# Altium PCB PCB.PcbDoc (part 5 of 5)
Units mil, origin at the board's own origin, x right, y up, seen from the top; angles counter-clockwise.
Board outline 8070.87 x 4448.94 mil, 4 copper layers (Top Layer, Layer 1, Layer 2, Bottom Layer), stack 23.756 mil thick; 263 components, 330 nets, 1677 pads, 1186 vias.
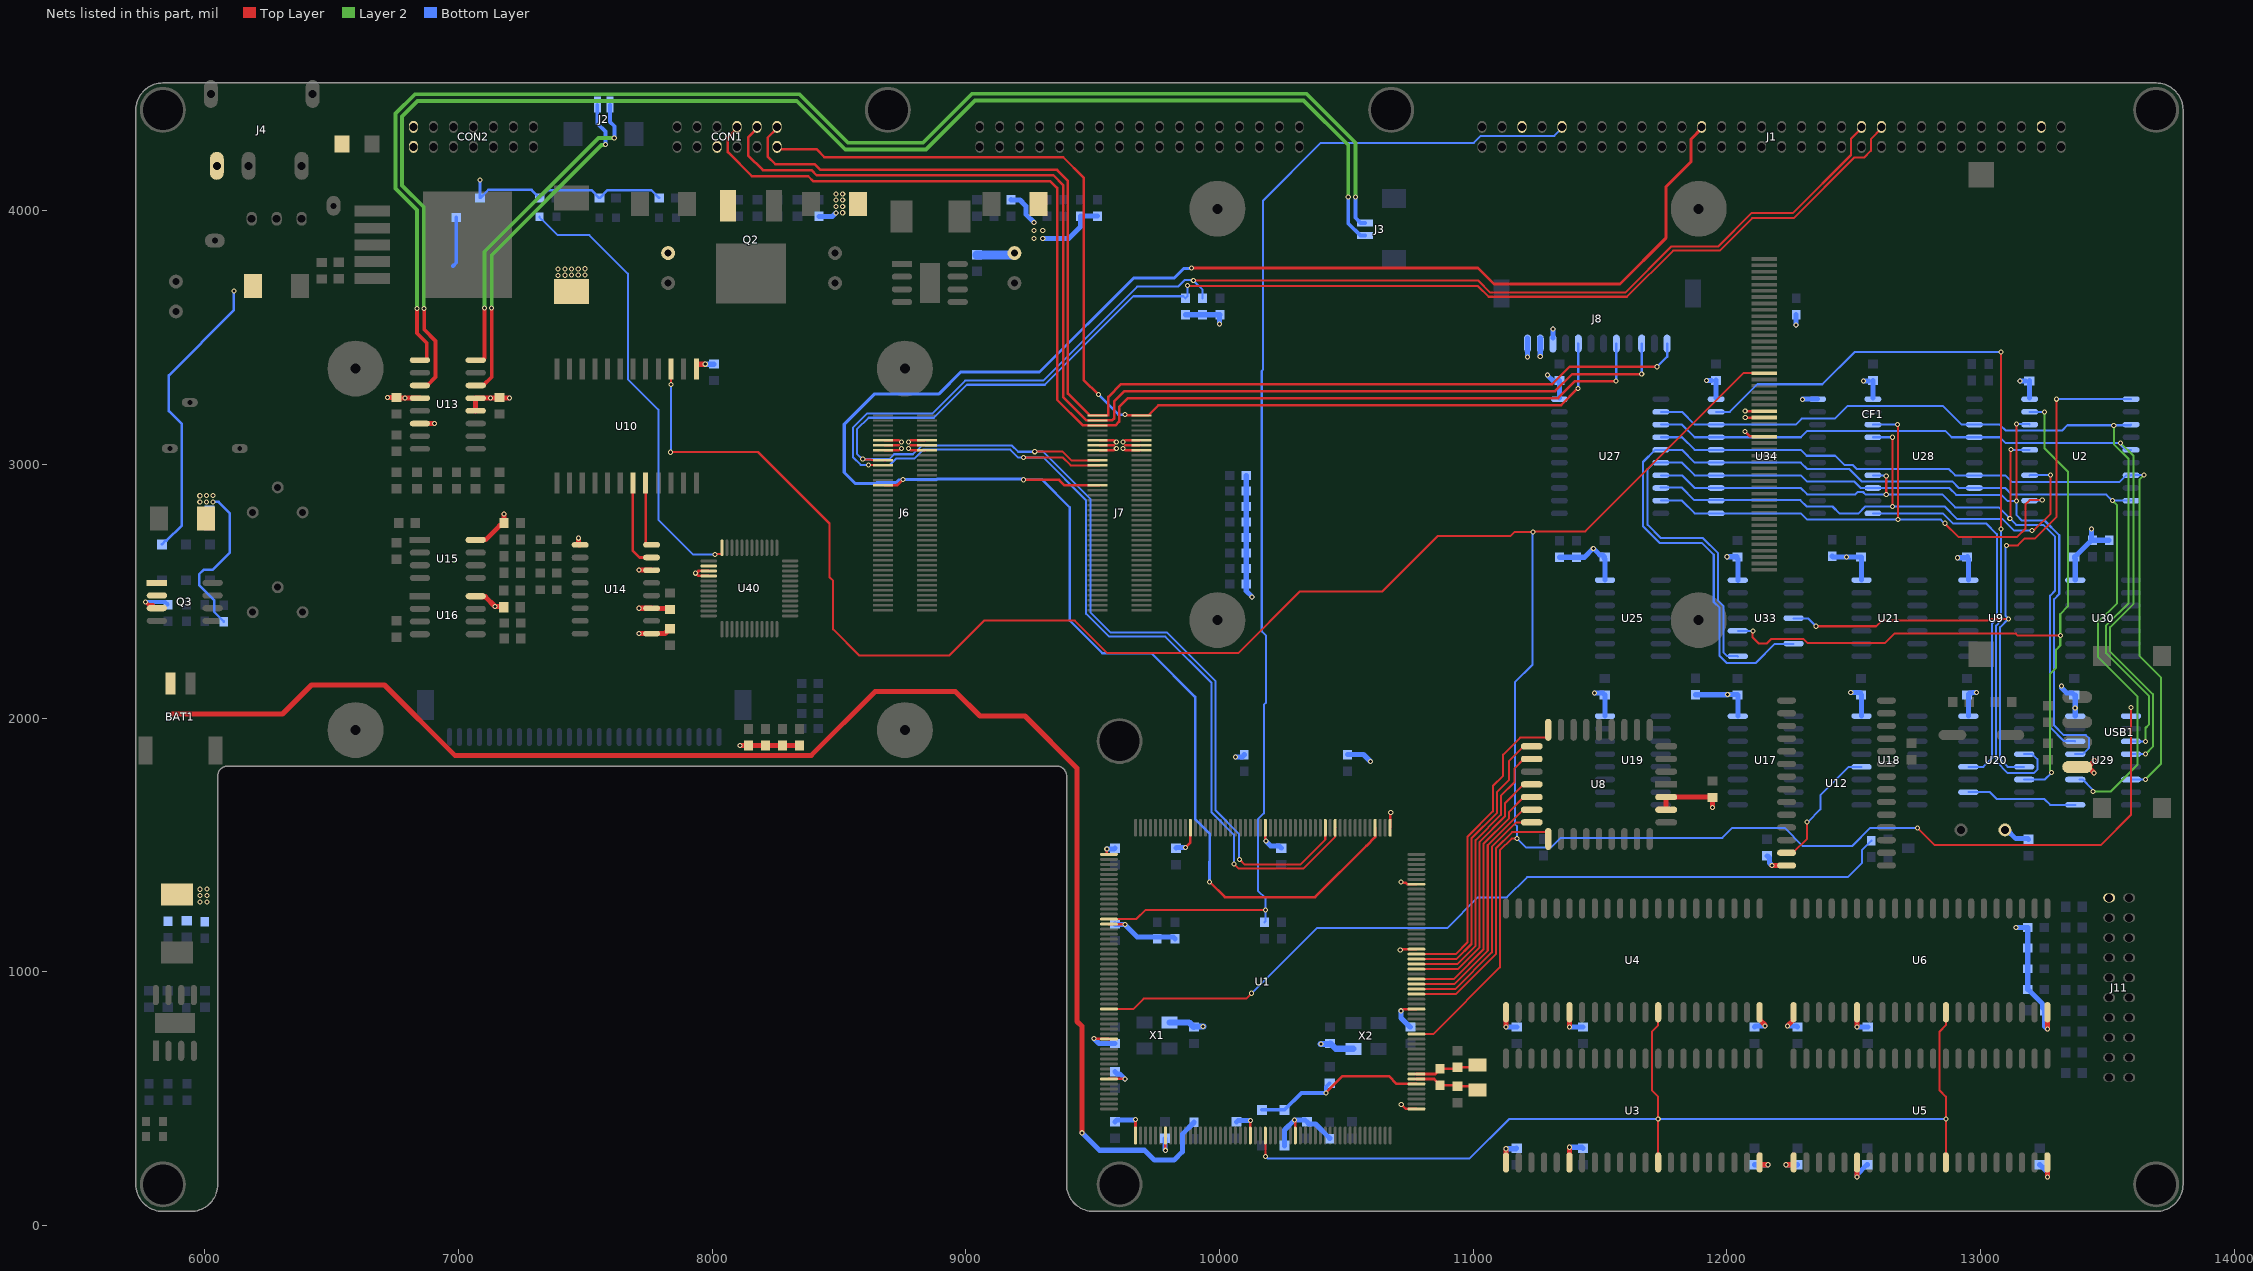
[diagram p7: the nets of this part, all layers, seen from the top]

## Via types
v1: diameter 20, hole 12, Top Layer to Bottom Layer, tented both sides, 1165 vias
v2: diameter 19.68, hole 11.81, Top Layer to Bottom Layer, tented both sides, 10 vias
v3: diameter 27.56, hole 27.56, Top Layer to Bottom Layer, 4 vias
v4: diameter 35.43, hole 35.43, Top Layer to Bottom Layer, 2 vias
v5: diameter 55.12, hole 55.12, Top Layer to Bottom Layer, 2 vias
v6: diameter 66.93, hole 66.93, Top Layer to Bottom Layer, 2 vias
v7: diameter 78.74, hole 78.74, Top Layer to Bottom Layer, 1 vias

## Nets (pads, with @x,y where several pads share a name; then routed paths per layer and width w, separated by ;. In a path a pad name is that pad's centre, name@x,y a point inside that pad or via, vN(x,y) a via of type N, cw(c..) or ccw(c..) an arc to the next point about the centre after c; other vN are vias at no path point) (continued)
RESET#: CF1.41 U1.120 U10.3 U29.1 | length 11067.3
  Top Layer w8: v1(7836,3048) 7837,3049 8181,3049 8463,2767 8463,2555 8477,2541 8477,2350 8581,2246 8934,2246 9072,2384 9430,2384 9558,2256 10073.52,2256 10316.52,2499 10642,2499 10860,2717 11147,2717 11164,2734 v1(11236,2734) 11238.3,2736.3 11442.41,2736.3 12065.76,3359.65 CF1.41@12147.64,3359.65 ; v1(7838,3315) U10.3@7838,3375.82 ; U1.120@10776.77,754.25 10842.62,754.25 11106,1017.63 11106,1478.98 11152,1524.98 v1(11174,1525) ; v1(12753,1566) 12819,1500 13476,1500 13594,1618 v1(13594,2042)
  Bottom Layer w8: v1(7836,3048) 7838,3050 v1(7838,3315) ; v1(11236,2734) 11234.42,2732.43 11234.42,2210.43 11165,2141 11165,1582 11174,1573 v1(11174,1525) 11210,1489 11306,1489 11345,1528 11982.63,1528 12021.63,1567 12228.37,1567 12300.37,1495 12494,1495 12566,1567 12752,1567 v1(12753,1566) ; U29.1@13594.02,2007.8 v1(13594,2042)
RPA: U20.4 U34.19 | length 3133
  Top Layer w8: v1(13081,2746) v1(13081,3444)
  Bottom Layer w8: U34.19@11958.27,3207.09 12012.09,3207.09 12121,3316 12377,3316 12504,3443 13080,3443 v1(13081,3444) ; v1(13081,2746) 13081,2383.63 13062,2364.63 13062,1829 13108,1783 13211,1783 13225,1797 13225,1838 13205.2,1857.8 U20.4@13172.76,1857.8
RPB: U2.1 U20.5 U33.4 | length 2844.4
  Top Layer w8: v1(12352,2362) 12589,2362 12611,2384 13028.74,2384 13035.74,2391 v1(13111,2391) ; v1(13103,2681) 13147.89,2681 13173.89,2707 13214,2707 13301,2794 v1(13301,3257)
  Bottom Layer w8: U33.4@12263.78,2392.52 12321.48,2392.52 v1(12352,2362) ; v1(13103,2681) 13100.7,2678.7 13100.7,2672.02 13099,2670.31 13099,2403 v1(13111,2391) 13078,2358 13078,1837 13107.2,1807.8 U20.5@13172.76,1807.8 ; v1(13301,3257) v1(13301,3257) 13594.44,3257.05 U2.1@13594.49,3257.09
RPC: U2.19 U20.6 U33.10 | length 3014.2
  Top Layer w8: v1(12104,2343) 12101.7,2340.7 12101.7,2317.92 12125.63,2294 12158.49,2294 12176.49,2312 12302.26,2312 12319.26,2295 12623,2295 12661,2333 13139.63,2333 13147.63,2325 13315,2325 v1(13316,2326)
  Layer 2 w8: v1(13252.85,3206.96) 13253,3206.8 13253,3064 13345,2972 13345,2440 13315,2410 13315,2326 13315,2286 13299,2270 13299,2198.37 13275,2174.37 13275,1794.25 13281,1788.25 v1(13281,1785)
  Bottom Layer w8: U33.10@12043.78,2342.52 12044.02,2342.76 12103.76,2342.76 v1(12104,2343) ; U20.6@13172.76,1757.8 13253.8,1757.8 v1(13281,1785) ; U2.19@13194.49,3207.09 13194.56,3207.03 v1(13252.85,3206.96) v1(13252.85,3206.96)
SMEMR#: J1.40 J6.60 J7.60 R59.1 U1.168 | length 8467.4
  Top Layer w8: v1(8616.94,2998) 8617.96,2996.98 J6.60@8680.18,2996.98 ; v1(9228,3027.86) 9381.51,3027.86 9413.31,2996.06 J7.60@9527.56,2996.06 ; v1(9897,3725) 11020.25,3725 11068.25,3677 11600,3677 11782,3859 11966,3859 12099,3992 12262.26,3992 12490,4219.74 12490,4283.31 12531.5,4324.8 J1.40@12531.5,4330.71 ; v1(10058,1424) 10076,1406 10330.3,1406 10455.96,1531.67 10455.96,1566.83 U1.168@10456.69,1567.56
  Bottom Layer w8: v1@8616,2998.38 8701.38,2998.38 8727,3024 8798.37,3024 8832.37,3058 9175.63,3058 9205.76,3027.86 v1(9228,3027.86) 9304.88,3027.86 9475,2857.75 9475,2411.05 9565.4,2320.65 9787.35,2320.65 9969,2139 9969,1628.92 10057.28,1540.64 10057.28,1424.72 v1(10058,1424) ; v1(8616.94,2998) 8616.57,2998.38 8585.89,2998.38 8555,3029.27 8555,3144.63 8610.37,3200 8868,3200 8998,3330 9305.08,3330 9676.08,3701 9836.63,3701 9862.63,3727 9895,3727 v1(9897,3725) 9934,3688 R59.1@9934,3655
SMEMW#: J1.42 J6.62 J7.62 R58.1 U1.170 | length 8354.5
  Top Layer w8: v1(8594,3021.38) 8595.38,3020 8626.06,3020 8629.58,3016.47 8680.38,3016.47 J6.62@8681.09,3015.76 ; v1(9272,3050) 9382,3050 9416.25,3015.75 J7.62@9527.56,3015.75 ; v1(9874,3705) 9876,3703 11019.63,3703 11061.63,3661 11606.63,3661 11788.63,3843 11972.63,3843 12100.63,3971 12263.89,3971 12502.89,4210 12542,4210 12568,4236 12568,4282.57 12610.24,4324.8 J1.42@12610.24,4330.71 ; v1(10079.28,1442.85) 10100.13,1422 10318.51,1422 10417.32,1520.81 U1.170@10417.32,1567.56
  Bottom Layer w8: v1@8593.5,3020.38 8698.38,3020.38 8718,3040 8791.75,3040 8825.75,3074 9182.25,3074 9206.32,3049.93 9271.93,3049.93 v1(9272,3050) ; v1(8594,3021.38) 8591.62,3021.38 8571,3042 8571,3138 8617,3184 8874.63,3184 9004.63,3314 9311.71,3314 9660.71,3663 9858,3663 R58.1@9866,3655 9874,3663 v1(9874,3705) ; v1@9272.07,3050 9305.37,3050 9491,2864.37 9491,2417.68 9571.68,2337 9793.63,2337 9985,2145.63 9985,1635.55 10078,1542.55 10078,1444.13 v1(10079.28,1442.85)
SMP1: U10.20 U14.8 | length 264.1
  Top Layer w10: U10.20@7738,2927 7738,2688.54 7743.54,2683 U14.8@7761.34,2683
SMP2: U10.19 U14.7 | length 352.1
  Top Layer w10: U10.19@7688,2927 7688,2659 7714,2633 U14.7@7761.34,2633
SPKL+: J3.1 U13.1 | length 5444.9
  Top Layer w15: v1(6836,3614) 6836.96,3613.04 6836.96,3517.04 6875.11,3478.89 6875.11,3414.43 6871.87,3411.2 U13.1@6848,3411.2
  Layer 2 w15: v1(6836,3614) 6836,4003 6751.84,4087.16 6751.84,4382.84 6828.16,4459.16 8344.84,4459.16 8536,4268 8832,4268 9025.16,4461.16 10342.84,4461.16 10536,4268 v1(10536,4055)
  Bottom Layer w15: v1(10536,4055) 10536,3972.35 10556.26,3952.09 J3.1@10573.98,3952.09
SPKL-: J3.2 U13.3 | length 5540.1
  Top Layer w15: U13.3@6848,3311.2 6877,3311.2 6910,3344.2 6910,3487 6864.96,3532.04 6864.96,3613.04 v1(6864,3614)
  Layer 2 w15: v1(6864,3614) 6863.16,3614.84 6863.16,4014.84 6778,4100 6778,4372 6839,4433 8334,4433 8525.16,4241.84 8842.84,4241.84 9036,4435 10332,4435 10508,4259 v1(10508,4054)
  Bottom Layer w15: v1(10508,4054) 10508,3950.35 10556.26,3902.09 J3.2@10573.98,3902.09
SPKR: R3.1 U1.32 | length 3311
  Top Layer w8: U1.32@9564.65,852.68 9659.68,852.68 9701,894 10106,894 v1(10127,915)
  Bottom Layer w8: v1(10127,915) 10384,1172 10898,1172 11019,1293 11133,1293 11213,1373 12478,1373 12533,1428 12533,1478.5 12570,1515.5 R3.1@12570,1517
SPKR+: J2.1 U13.16 | length 1291.7
  Top Layer w15: U13.16@7068,3411.2 7095.11,3411.2 7103.08,3419.17 v1@7103.08,3615.72
  Layer 2 w15: v1(7103.08,3617.07) 7103.08,3838.08 7552.4,4287.4 v1(7614.17,4287.4)
  Bottom Layer w15: J2.1@7597.44,4418.31 7597.44,4350.56 7615,4333 7615,4288.23 v1(7614.17,4287.4)
SPKR-: J2.2 U13.14 | length 1357.7
  Top Layer w15: U13.14@7068,3311.2 7070.29,3313.48 7099.29,3313.48 7131,3345.2 7131,3616.92 v1(7131.08,3617)
  Layer 2 w15: v1@7131,3617.07 7131,3826 7564.44,4259.44 7578.22,4259.44 v1(7579.17,4260.4)
  Bottom Layer w15: J2.2@7547.44,4418.31 7547.44,4344.56 7580,4312 7580,4261.23 v1(7579.17,4260.4)
SYSCLK: J1.24 J6.52 J7.52 U1.160 | length 8263.9
  Top Layer w10: J6.52@8681.1,2917.32 8729.66,2917.32 v1(8752,2939.66) ; v1(9228,2939.6) 9261.67,2939.6 9262.47,2938.8 9368.2,2938.8 9389.68,2917.32 J7.52@9527.56,2917.32 ; v1(9961,1354) 9962,1354 10022,1294 10377,1294 10579,1496 10579.19,1496 10613.83,1530.63 10613.83,1567.21 U1.160@10614.17,1567.56
  Top Layer w12: v1(9890,3774) 11019.34,3774 11082.34,3711 11579,3711 11760,3892 11760,4094 11860,4194 11860,4283.23 11901.57,4324.8 J1.24@11901.57,4330.71
  Bottom Layer w10: v1(9228,2939.6) 9228.93,2938.66 9302.16,2938.66 9410,2830.82 9410,2384.12 9538.62,2255.51 9731.92,2255.51 9904,2083.43 9904,1602 9961.5,1544.5 9961.5,1434.82 9961,1434.32 v1(9961,1354)
  Bottom Layer w12: v1(8752,2939.66) 8750.47,2938.13 8735.68,2938.13 8725.77,2928.23 8647.97,2928.23 8644.75,2925 8564.29,2925 8521,2968.29 8521,3158.71 8639.29,3277 8893.37,3277 8980.37,3364 9290.99,3364 9661.99,3735 9743.62,3735 9822.54,3735 9860.54,3773 9889,3773 v1(9890,3774) ; v1@8752.07,2939.66 8884.7,2939.66 8888.03,2943 9222.43,2943 9225.84,2939.6 v1(9228,2939.6)
TC: J1.10 R10.2 U1.14 | length 4815.6
  Top Layer w8: U1.14@9564.65,1207.01 9565.37,1207.74 9672.85,1207.74 9709.11,1244 v1(10182,1244)
  Bottom Layer w8: R10.2@10178,1195 10182,1199 v1(10182,1244) 10182,1290 10152,1320 10152,1601 10175,1624 10175,2052.33 10183,2060.33 10183,2326 10167,2342 10167,3368.94 10172,3373.94 10172,4040 10399.97,4267.97 11003.5,4267.97 11030.62,4295.09 11320.68,4295.09 11350.39,4324.8 J1.10@11350.39,4330.71
TD0: U2.3 U27.2 U28.3 U29.3 U34.18 | length 3393.6
  Layer 2 w8: v1(13526,3153) 13526,3079.89 13584,3021.89 13584,2453.12 13496,2365.12 13496,2255.37 13664,2087.37 13664,1973.89 13651,1960.89 v1(13651,1908)
  Bottom Layer w8: U27.2@11740.16,3207.09 11823.91,3207.09 11873.91,3157.09 U34.18@11958.27,3157.09 12272.09,3157.09 12295.09,3180.09 12426.09,3180.09 12477,3231 12852,3231 12925.91,3157.09 U28.3@12976.38,3157.09 13076.91,3157.09 13101,3133 13322,3133 13343.42,3154.42 13591.81,3154.42 U2.3@13594.49,3157.09 ; U29.3@13594.11,1907.9 13650.9,1907.9 v1(13651,1908)
TD1: U2.5 U27.3 U28.4 U29.4 U34.17 | length 3345.2
  Layer 2 w8: v1(13553,3084) 13604,3033 13604,2450.49 13512,2358.49 13512,2262 13680,2094 13680,1887 v1(13651,1858)
  Bottom Layer w8: U27.3@11740.16,3157.09 11823.91,3157.09 11873.91,3107.09 U34.17@11958.27,3107.09 12292.09,3107.09 12317,3132 12862,3132 12886.91,3107.09 U28.4@12976.38,3107.09 13076.91,3107.09 13100.5,3083.5 13552.5,3083.5 v1(13553,3084) 13555.3,3081.7 13555.3,3073.82 13572.02,3057.09 U2.5@13594.49,3057.09 ; U29.4@13594.11,1857.9 13650.9,1857.9 v1(13651,1858)
TD2: U2.7 U27.4 U28.7 U29.6 U34.16 | length 3313
  Layer 2 w8: v1(13645,2958) 13628,2941 13628,2244.37 13712,2160.37 13712,1819 v1(13651,1758)
  Bottom Layer w8: U27.4@11740.16,3107.09 11823.91,3107.09 11873.91,3057.09 U34.16@11958.27,3057.09 12291.91,3057.09 12314.91,3034.09 12427.79,3034.09 12463.89,2998 12496,2998 12512,2982 12876,2982 12900.91,2957.09 U28.7@12976.38,2957.09 13097.91,2957.09 13124,2931 13549.11,2931 13575.21,2957.09 U2.7@13594.49,2957.09 13594.94,2957.55 13644.55,2957.55 v1(13645,2958) ; U29.6@13594.11,1757.9 13650.9,1757.9 v1(13651,1758)
TD3: U2.9 U27.5 U28.8 U29.11 U33.6 U34.15 | length 4790.7
  Layer 2 w8: v1(13444,1710) 13513,1710 13620,1817 13620,2084.75 13463.03,2241.72 13463.03,2377.4 13539,2453.37 13539,2839 v1(13520.91,2857.09)
  Bottom Layer w8: U33.6@12263.78,2292.52 12189.52,2292.52 12114,2217 11999.63,2217 11972,2244.63 11972,2434.63 11949,2457.63 11949,2644.37 11902.37,2691 11735,2691 11670,2756 11670,3009.4 11717.69,3057.09 U27.5@11740.16,3057.09 11823.91,3057.09 11873.91,3007.09 U34.15@11958.27,3007.09 12291.91,3007.09 12317,2982 12482.37,2982 12531.37,2933 12889,2933 12914.91,2907.09 U28.8@12976.38,2907.09 13097.91,2907.09 13124,2881 13497,2881 v1(13520.91,2857.09) U2.9@13594.49,2857.09 ; U29.11@13391,1757.8 13403.02,1757.8 13441.7,1719.11 13441.7,1712.3 v1(13444,1710)
TD4: U2.18 U27.6 U28.13 U29.13 U33.8 U34.14 | length 4170
  Top Layer w8: v1(13142,3160) 13142.55,3159.45 13142.55,2855.49 v1(13143.1,2854.93)
  Bottom Layer w8: U33.8@12043.78,2242.52 12041.2,2245.1 12000.83,2245.1 11988,2257.92 11988,2441.25 11965,2464.25 11965,2651 11906,2710 11740,2710 11688.69,2761.31 11688.69,2981.69 11714.09,3007.09 U27.6@11740.16,3007.09 11823.91,3007.09 11873.91,2957.09 U34.14@11958.27,2957.09 12291.91,2957.09 12317,2932 12504,2932 12528.91,2907.09 U28.13@12576.38,2907.09 12877.91,2907.09 12904.91,2880.09 13082.91,2880.09 13108.07,2854.93 v1(13143.1,2854.93) 13143.1,2799.9 13164,2779 13253,2779 13311,2721 13311,2489 13291,2469 13291,1970.63 13328.63,1933 13416,1933 13429,1920 13429,1883 13403.8,1857.8 U29.13@13374.02,1857.8 ; v1(13142,3160) 13143.45,3158.55 13193.04,3158.55 U2.18@13194.49,3157.09
TD5: U2.16 U27.7 U28.14 U29.14 U34.13 | length 3019.7
  Top Layer w8: v1(12629,2881) v1(12629,2955) ; v1(13116,2787) 13118,2789 13118,3056 v1(13120,3058)
  Bottom Layer w8: U27.7@11740.16,2957.09 11823.91,2957.09 11873.91,2907.09 U34.13@11958.27,2907.09 12291.91,2907.09 12317,2882 12506.89,2882 12515.98,2891.09 12537.39,2891.09 12547.48,2881 12628,2881 12629,2882 12850,2882 12901,2831 13072,2831 v1(13116,2787) 13141,2762 13247.37,2762 13295,2714.37 13295,2502.89 13275,2482.89 13275,1964 13329.84,1909.16 13372.66,1909.16 U29.14@13374.02,1907.8 ; U28.14@12576.38,2957.09 12577.43,2956.05 12627.95,2956.05 v1(12629,2955) ; v1(13120,3058) 13120.45,3057.55 13194.04,3057.55 U2.16@13194.49,3057.09
TD6: U2.14 U27.8 U28.17 U34.12 | length 2245.8
  Top Layer w8: v1(12653,2834) 12653.5,2834.5 12653.5,3106.5 v1(12654,3107) ; v1(13204,2740) 13206.3,2742.3 13213.3,2742.3 13277,2806 v1(13277,2959)
  Bottom Layer w8: U27.8@11739,2909 11822.75,2909 11872.75,2859 11958.27,2859 12290.75,2859 12315.84,2833.91 12417.21,2833.91 12445.11,2806 12519,2806 12546.91,2833.91 12653,2833.91 12858.84,2833.91 12908.65,2784.09 13087.79,2784.09 13131.89,2740 v1(13204,2740) ; U28.17@12576.38,3107.09 12576.43,3107.05 v1(12654,3107) v1(12654,3107) ; U2.14@13194.49,2957.09 13195.44,2958.05 13276.05,2958.05 v1(13277,2959)
TD7: U2.12 U27.9 U28.18 U34.11 | length 2204.2
  Top Layer w8: v1(12674,3157) 12676,3155 12676,2783 v1(12675,2782) ; v1(12860,2768) 12860,2767 12913,2714 13145,2714 13178,2747 13178,2843 13194,2859 v1(13244,2859)
  Bottom Layer w8: U27.9@11740.16,2857.09 11823.91,2857.09 11873.91,2807.09 U34.11@11958.27,2807.09 12291.91,2807.09 12317,2782 v1(12675,2782) 12843.89,2782 12857.89,2768 v1(12860,2768) ; U28.18@12576.38,3157.09 12576.43,3157.05 v1(12674,3157) v1(12674,3157) ; U2.12@13194.49,2857.09 13195.44,2858.05 13243.05,2858.05 v1(13244,2859)
TURBO: U40.14
USBCS#: U12.27 U18.12 | length 506.7
  Top Layer w8: U12.27@12236.22,1468.9 12261.12,1468.9 12317,1524.78 v1(12317,1590)
  Bottom Layer w8: v1(12317,1590) 12319,1590 12369,1640 12369,1696 12480.8,1807.8 U18.12@12531.5,1807.8
V3.7V: BAT1.2 C29.1 L5.1 Q3.1 Q3.2 Q3.3 R2.1 R27.2 R133.1 R135.2 | length 6121.7
  Top Layer w15: v1(5766,2458) 5767.35,2458 5778.35,2447 5796,2447
  Top Layer w20: 5871.5,2015.75 6306.75,2015.75 6421,2130 6708.58,2130 6985.58,1853 8391,1853 8642,2104 8960,2104 9056,2008 9233.35,2008 9439,1802.35 9439,804 9458,785 v1(9458,365)
  Bottom Layer w15: v1(5766,2458) 5766.96,2457.04 5844.33,2457.04 5854.33,2447.04 R27.2@5854.33,2446.89
  Bottom Layer w20: v1(9458,365) 9527,296 9705,296 9744,257 9821,257 9854,290 9854,359.5 9900,405.5 R2.1@9900,407
  other v1: 5981.48,1275.33 6007.87,1275.59 5981.48,1300.22 6007.87,1300.48 5981.48,1325.11 6007.87,1325.37
VCC: C1.2 C2.2 C10.1 C11.1 C12.1 C13.1 C14.1 C15.1 C16.1 C17.1 C24.1 C25.1 C30.1 C31.1 C52.2 C54.2 C59.2 C60.2 C61.2 C68.1 C72.1 C73.1 C74.1 C75.1 C76.1 C77.1 C78.1 C80.1 C83.1 C84.1 C85.1 C86.1 C87.1 C88.1 C89.1 C90.1 C91.1 C92.1 C93.1 C94.1 C95.1 C96.1 C97.1 C98.1 C99.1 C100.1 C101.1 C102.1 C103.1 C104.2 C105.2 CF1.13 CF1.36 CF1.38 CON1.5 CON2.1 CON2.2 D4.K D5.K D12.A J1.6 J1.58 J6.65 J6.66 J6.67 J6.68 J6.69 J6.70 J7.65 J7.66 J7.67 J7.68 J7.69 J7.70 J8.1 J8.2 J8.3 J11.1 R1.1 R44.2 R45.2 R46.2 R47.2 R48.2 R49.2 R50.2 R51.2 R52.2 R53.2 R54.2 R55.2 R56.2 R57.2 R58.2 R59.2 R60.2 R61.2 R62.2 R63.2 R64.2 R65.2 R66.2 R67.2 R68.2 R69.2 R70.2 R100.1 R102.2 R103.2 R104.2 R105.2 R106.2 R107.2 R136.1 R137.1 R138.1 R139.1 SP1.1 U1.1 U1.15 U1.38 U1.46 U1.53 U1.59 U1.76 U1.85 U1.105 U1.125 U1.137 U1.150 U1.157 U1.182 U1.197 U2.20 U3.1 U3.6 U3.21 U4.1 U4.6 U4.21 U5.1 U5.6 U5.21 U6.1 U6.6 U6.21 U8.31 U8.32 U9.14 U10.1 U12.28 U13.4 U13.6 U13.12 U13.13 U14.1 U14.3 U14.6 U14.9 U15.8 U16.8 U17.16 U18.16 U19.16 U20.16 U21.14 U25.14 U27.20 U28.20 U29.16 U30.14 U33.14 U34.1 U34.20 U40.15 U40.16 USB1.VCC X1.4 X2.4 | length 11745.2
  Top Layer w10: v1(7934,2571) 7936.71,2571 7945.6,2579.9 7949.09,2579.9 ; U40.16@7986.57,2560.21 7986.22,2560.56 7947.15,2560.56 7938.45,2569.26 7949.09,2579.9 ; U40.15@7986.57,2579.9 7949.09,2579.9 ; J6.66@8681.1,3055.12 8736.49,3055.12 ; J6.68@8681.1,3074.8 8736.49,3074.8 ; J6.70@8681.1,3094.49 8736.49,3094.49 ; 8783.2,3055.12 J6.65@8838.58,3055.12 ; 8783.2,3074.8 J6.67@8838.58,3074.8 ; 8783.2,3094.49 J6.69@8838.58,3094.49 ; v1(9506,736) 9507.09,734.91 9564.47,734.91 U1.38@9564.73,734.65 ; J7.66@9527.56,3055.12 9582.94,3055.12 ; J7.68@9527.56,3074.8 9582.94,3074.8 ; J7.70@9527.56,3094.49 9582.94,3094.49 ; v1(9556,1484) 9556,1463.75 9556.75,1463 U1.1@9564.73,1463 ; U1.46@9564.73,577.17 v1@9627.12,577.17 ; U1.15@9564.82,1187.32 9565.17,1186.98 9625.76,1186.98 v1(9627,1185.74) ; 9629.65,3055.12 J7.65@9685.04,3055.12 ; 9629.65,3074.8 J7.67@9685.04,3074.8 ; 9629.65,3094.49 J7.69@9685.04,3094.49 ; U1.53@9669.2,354.42 v1@9669.2,416.8 ; v1(9787,296) 9787.2,296.2 9787.2,354.3 U1.59@9787.4,354.5 ; v1(9866,1490) 9885.48,1509.48 9885.48,1567.21 U1.197@9885.83,1567.56 ; U1.76@10122.02,354.35 v1(10122,414) ; U1.182@10181.19,1567.47 10181.45,1567.21 10181.45,1516.55 v1(10183,1515) ; v1(10296.9,416) 10296.9,413.29 10299.21,410.98 U1.85@10299.21,354.5 ; U1.157@10673.31,1567.47 U1.157@10673.23,1567.56 10673.23,1622.98 10675.54,1625.29 v1(10675.54,1628) ; v1(10713,1086) 10715.71,1086 10718.6,1088.9 U1.137@10776.5,1088.9 ; v1(10716,846) 10718.71,846 10725.38,852.68 10776.6,852.68 U1.125@10776.68,852.59 ; v1(10716,1353) 10717.91,1351.09 10733.91,1351.09 10739.85,1345.15 10776.25,1345.15 U1.150@10776.68,1344.72 ; v1(10717,477) 10734.68,459.32 10776.25,459.32 U1.105@10776.68,458.89 ; v1(12072,3130) 12090.1,3111.9 12145.39,3111.9 CF1.36@12147.55,3109.73 ; v1(12073,3210) 12073.18,3209.82 12147.46,3209.82 CF1.38@12147.64,3209.65 ; v1@12073.27,3184.73 CF1.13@12147.55,3184.73
  Top Layer w20: v1(6721,3263) 6755.13,3263 C54.2@6755.91,3263.78 6758.68,3261 v1(6790,3261) ; v1@6787.22,3261.58 6847.62,3261.58 U13.4@6848,3261.2 ; U13.6@6848,3161.2 6848.2,3161 v1(6905,3161) ; U16.8@7068,2480.38 7097.08,2480.38 7099.08,2478.38 7105.62,2478.38 v1(7144,2440) 7176.02,2440 C68.1@7179.02,2437 ; U15.8@7068,2702.38 7068.77,2703.14 7107.14,2703.14 7162.38,2758.38 7170.99,2758.38 7179.49,2766.88 C61.2@7179.49,2768.38 7179,2768.87 v1(7179,2805) ; U13.12@7068,3211.2 U13.13@7068,3261.2 v1@7129.78,3261.2 ; v1(7127,3261) 7158.64,3261 C52.2@7161.42,3263.78 ; C52.2@7161,3261.2 7200.8,3261.2 v1(7201,3261) ; v1(7474,2709) 7474,2683.92 7474.92,2683 U14.9@7480,2683 ; v1(7711,2333) U14.1@7761.34,2333 7761.72,2333.38 7813.88,2333.38 7832.5,2352 C60.2@7834,2352 ; v1(7711,2433) U14.3@7761.34,2433 7761.72,2432.62 7829.63,2432.62 C59.2@7834.25,2428 ; v1(7711,2583) U14.6@7761.34,2583 ; U10.1@7938,3375.82 7938,3395 v1(7973,3395) ; v1(8110,1892) R48.2@8210.67,1892 R47.2@8277.33,1892 R46.2@8344,1892 ; U3.1@11130,248 v1(11130,302) ; v1(11130,782) U4.1@11130,840 ; U3.6@11380,248 11380,307 v1(11381,308) ; v1(11380,782) U4.6@11380,840 ; U8.31@11762.41,1639.58 U8.31@11761.46,1638.62 U8.32@11761.46,1688.62 11942.38,1688.62 C31.1@11944,1687 v1(11944,1647) ; U3.21@12130,248 12130,240.85 12131.85,239 v1(12163,239) ; U4.21@12130,840 12130,810.92 12151,789.92 v1(12151,786) ; v1(12179,1419) 12179.1,1418.9 U12.28@12236.22,1418.9 ; v1(12234,239) 12262.15,239 12264,240.85 U5.1@12264,248 ; v1(12239,786) 12264,811 U6.1@12264,840 ; v1(12514,190) U5.6@12514,248 ; v1(12514,782) U6.6@12514,840 ; v1(13264,190) U5.21@13264,248 ; v1(13264,774) U6.21@13264,840 ; USB1.VCC@13421,1809 13426,1809 v1(13449,1832) ; USB1.VCC@13422.78,1809 13447.78,1784 v1(13448,1784)
  Bottom Layer w8: C73.1@12528.94,2634.94 C73.1@12529,2635 C73.1@12531.5,2632.5
  Bottom Layer w10: v1(7085,4122) R139.1@7085,4051 7086.5,4051 7117.5,4082 7288.17,4082 7319.17,4051 R138.1@7320.67,4051 7322.17,4051 7352.67,4081.5 7524.33,4081.5 7554.83,4051 R137.1@7556.33,4051 7557.83,4051 7588.33,4081.5 7760,4081.5 7790.5,4051 R136.1@7792,4051
  Bottom Layer w20: v1(7973,3395) 8007,3395 C105.2@8008,3396 ; R57.2@8422,3978 8474.64,3978 v1(8488.61,3991.97) ; R100.1@9177.86,4044 9179.5,4042.36 9213.64,4042.36 9237,4019 9237,3986.35 v1(9269.61,3953.74) ; v1(9303.61,3890.24) 9406.24,3890.24 9452.67,3936.67 R62.2@9452.67,3979 R55.2@9519,3979 ; v1(9506,736) 9525,717 C94.1@9588.25,717 ; v1(9556,1484) 9585,1484 C17.1@9588,1487 ; C98.1@9588,408 9596,416 v1@9667.61,416 ; C95.1@9588,606 9596.5,597.5 9606.97,597.5 v1(9627.2,577.26) ; C83.1@9588,1188 9590.26,1185.74 v1(9627,1185.74) 9675.74,1137 9818,1137 R52.2@9825,1130 ; C101.1@9786,343.04 9786,297 v1(9787,296) ; C96.1@9828.26,1487 9831.26,1490 v1(9866,1490) ; R58.2@9866,3590 R59.2@9934,3590 ; R59.2@9938.59,3590 R54.2@10002,3590 10001,3589 v1(10001,3554) ; v1(10063,1847) 10090.5,1847 10098,1854.5 R51.2@10098,1856 ; C102.1@10068,408 10074,414 v1(10122,414) ; R64.2@10106,2956 R65.2@10106,2895 R66.2@10106,2834 R67.2@10106,2773 R68.2@10106,2712 R69.2@10106,2651 R70.2@10106,2590 R45.2@10106,2529 10106,2501 v1(10129,2478) ; v1(10183,1515) 10202.52,1495.48 10235.5,1495.48 C97.1@10244,1486.98 ; D12.A@10257,314 10257,376.1 v1(10296.9,416) 10336.98,416 C99.1@10345,407.98 10353.5,399.48 10379.02,399.48 10435,343.5 R1.1@10435,342 ; R53.2@10505,1856 10568,1856 v1(10595.49,1828.51) ; v1(10716,846) 10716,817.46 10751.5,781.96 C93.1@10753,781.96 ; v1(11130,302) 11170.04,302 C11.1@11172,303.96 ; v1(11130,782) v1(11130,782) C16.1@11172.25,781.96 ; v1(11214,3423) J8.1@11214,3498 ; v1(11265,3425) J8.2@11265,3498 ; v1(11293,3352) 11316,3329 C84.1@11323.14,3329 ; J8.3@11315,3499 v1(11315,3533.8) ; U27.20@11340.16,3261 C84.1@11340.16,3331 ; R60.2@11341,2634 R61.2@11408,2634 11438.99,2634 v1(11473.99,2669.01) 11499.5,2643.5 11510.5,2643.5 C77.1@11519,2635 ; v1(11380,782) C2.2@11433,781.98 ; v1(11381,308) 11428.96,308 C10.1@11433,303.96 ; v1(11478,2099.5) 11511.51,2099.5 11520.16,2090.86 U19.16@11520.16,2007.8 ; C77.1@11516.66,2636.26 11516.66,2630.25 11520.16,2626.75 U25.14@11520.16,2543.7 ; R50.2@11877,2092 12003,2092 v1(12004,2093) 12041.64,2093 12043.78,2090.86 U17.16@12043.78,2007.8 ; v1(11920.1,3330.7) C72.1@11940.57,3330.7 ; U34.20@11957.59,3261 C72.1@11957.59,3332.7 ; v1(12002,2636) 12041,2636 12041,2629.99 12044.5,2626.5 U33.14@12044.5,2543.44 ; C1.2@12109.75,781.98 12113.77,786 v1(12151,786) ; C103.1@12110,239 v1(12163,239) ; C104.2@12159,1457 12160.5,1457 12169,1448.5 12169,1429 v1(12179,1419) ; v1(12234,239) C90.1@12279,239 ; v1(12239,786) 12274.96,786 C15.1@12279,781.96 ; v1(12273,3549) 12274,3550 R56.2@12274,3590 ; v1(12298,3256) 12299.09,3257.09 U34.1@12358.27,3257.09 ; R44.2@12416,2638 12419.06,2634.94 v1(12471.94,2634.94) C73.1@12528.94,2634.94 ; v1(12489,2100.36) 12528,2100.36 12528,2094.35 12531.5,2090.86 U18.16@12531.5,2007.8 ; v1(12514,190) 12514,200.5 12552.5,239 C14.1@12554,239 ; v1(12514,782) C12.1@12556,781.96 C12.1@12556,781.96 ; C73.1@12529,2635 C73.1@12530.5,2635 ; U21.14@12531.5,2543.7 C73.1@12531.5,2632.5 ; v1(12538.89,3329) C78.1@12559.36,3329 ; U28.20@12576.38,3261 C78.1@12576.38,3331 ; v1(12910.26,2632) 12945,2632 12949.26,2636.26 12949.26,2630.25 12952.76,2626.75 U9.14@12952.76,2543.7 ; U20.16@12952.76,2007.8 12952.76,2094.26 12958,2099.5 12967.73,2099.5 12969.72,2101.49 v1(12984.49,2101.49) ; SP1.1@13097,1559 13105.44,1559 13140,1524.44 13187.56,1524.44 C30.1@13190,1522 ; v1(13140,1175) R106.2@13187,1175 R104.2@13186.97,929.82 ; v1(13157,3329) C80.1@13177.47,3329 ; R104.2@13186.97,929.82 13188.47,929.82 13245.5,872.8 13245.5,856.5 C13.1@13254,848 13254,784 v1(13264,774) ; U2.20@13194.49,3261 C80.1@13194.49,3331 ; C91.1@13234,239 13235.5,239 13264,210.5 v1(13264,190) ; v1(13320,2126) 13320,2119 13339.5,2099.5 13361.5,2099.5 C88.1@13370,2091 ; U29.16@13374.02,2007.8 v1(13374,2040) C88.1@13374,2090.84 ; U30.14@13374.02,2543.7 13374.02,2626.75 13370.52,2630.25 13370.52,2636.26 13372.75,2636.26 R107.2@13439.75,2703.25 ; R107.2@13439,2710 v1(13439,2745) ; R107.2@13442,2701 R103.2@13508,2701
  Bottom Layer w25: X1.4@9804,800 9880.46,800 9898.5,781.96 C87.1@9900,781.96 9902.04,784 v1(9935.88,784) ; v1(10400,715) 10434,715 C100.1@10436,717 10437.5,717 10458.86,695.64 X2.4@10528,695.64
  Bottom Layer w35: C25.1@9044,3826 9179.5,3826 9186.56,3833.06 C24.1@9192,3833.06
  other v1: 9669.12,416.89 8747,3062 8774,3062 9593.46,3062.44 9620.46,3062.44 8747,3088 8774,3088 9593.46,3088 9620.46,3088 12073.09,3184.91 9269.61,3891.24 9303.61,3921.49 9269.61,3922.49 8515,3992.23 8488.61,4016.86 8515,4017.11 8488.61,4041.74 8515,4042 8488.61,4066.63 8515,4066.89
VCMOS: C106.1 D11.K D12.K U1.110 | length 721.9
  Top Layer w10: v1(10420,522) 10420,523 10485,588 10668,588 10698.25,557.75 10776.43,557.75 U1.110@10776.77,557.4
  Bottom Layer w15: D11.K@10168,455.73 D12.K@10257,455.73 10323.27,522 v1(10420,522) 10420,546.5 10433.5,560 C106.1@10435,560
VGA_B1: CON1.8 J7.76 J8.8 | length 4807.2
  Top Layer w10: CON1.8@8098.43,4330.71 8098.43,4324.8 8062,4288.38 8062,4231 8157,4136 8379,4136 8399,4116 9334,4116 9360,4090 9360,3255 9461.46,3153.54 9527.56,3153.54 9527.64,3153.62 9589.62,3153.62 9605,3169 9605,3227 9639,3261 11335.26,3261 11402.26,3328 v1(11564,3328)
  Bottom Layer w10: v1(11564,3328) 11564.48,3328.48 11564.48,3475.9 J8.8@11564.96,3476.38
VGA_G1: CON1.10 J7.78 J8.10 | length 4808.3
  Top Layer w10: CON1.10@8177.17,4330.71 8177.17,4324.8 8142,4289.64 8142,4218 8200,4160 8392,4160 8412,4140 9345.36,4140 9385,4100.36 9385,3264 9475.77,3173.23 9527.56,3173.23 9527.64,3173.31 9577.31,3173.31 9585,3181 9585,3248 9625.75,3288.75 11323.76,3288.75 11391.01,3356 v1(11665,3356)
  Bottom Layer w10: v1(11665,3356) J8.10@11664.96,3476.38
VGA_R1: CON1.12 J7.80 J8.12 | length 4783.5
  Top Layer w10: CON1.12@8255.91,4330.71 8255.91,4324.8 8219,4287.9 8219,4214 8249,4184 8404,4184 8427,4161 9359.71,4161 9403,4117.71 9403,3279 9489.09,3192.91 9561.85,3192.91 9561.93,3192.99 9561.93,3265.93 9612.5,3316.5 11312.27,3316.5 11380.77,3385 v1(11726,3385)
  Bottom Layer w10: v1(11726,3385) 11765.48,3424.48 11765.48,3475.86 J8.12@11764.96,3476.38
VIN: D8.A D20.A FU1.1 J4.1 | length 1160.4
  Bottom Layer w10: D8.A@5830.71,2685.04 5845.39,2699.72 5849.33,2699.72 5909.45,2759.84 5909.45,3158.65 5858.27,3209.83 5858.27,3351.27 6115,3608 v1(6115,3683)
VIN5V: C21.1 C22.1 D7.A L3.1 Q2.2 R26.2 R124.2 | length 818.7
  Bottom Layer w10: v1(6033,2852) 6054,2852 6098,2808 6098,2651 6032,2585 5996,2585 5978,2567 5978,2524 6037,2465 6037,2419.19 6074.8,2381.38 R26.2@6074.8,2379.88
  Bottom Layer w15: 6978,3782 6991.09,3795.09 R124.2@6991.09,3973
  other v1: 5980.22,2851.49 6006.61,2851.74 5980.22,2876.37 6006.61,2876.63 6033,2876.89 7393.22,3745.49 7419.61,3745.74 7446,3746 7472.39,3746.26 7498.78,3746.51 7393.22,3770.37 7419.61,3770.63 7446,3770.89 7472.39,3771.14 7498.78,3771.4
VSYNC1: CON1.11 J7.79 J8.5 | length 4285.4
  Top Layer w10: CON1.11@8255.91,4251.97 8264.87,4243 8411,4243 8443,4211 9384.36,4211 9465,4130.36 9465,3333 v1(9523,3275) ; v1(9628,3196) 9630.71,3196 9633.71,3192.99 9684.96,3192.99 9685.04,3192.91 9719.33,3192.91 9719.41,3192.99 9719.41,3193.41 9759.25,3233.25 11346.75,3233.25 v1@11414,3300.5
  Bottom Layer w10: v1(9523,3275) 9602,3196 v1(9628,3196) ; v1(11414,3300) 11414.48,3300.48 11414.48,3475.9 J8.5@11414.96,3476.38
WEJ: U1.79 U3.13 U4.13 U5.13 U6.13 | length 4060.3
  Top Layer w8: v1(10181,272) 10181.05,272.05 U1.79@10181.1,354.33 U1.79@10181.1,354.33 ; U3.13@11730,248 11730,507 11705,532 11705,764 11730,789 U4.13@11730,840 ; U5.13@12864,248 12864,507 12839,532 12839,764 12864,789 U6.13@12864,840
  Bottom Layer w8: v1(10181,272) 10182.69,272 10191.69,263 10985.75,263 11141.75,419 v1(11730,419) v1@12865.12,419
  other v1: 12864,419
WPA: U20.12 U28.11 | length 1520.9
  Bottom Layer w8: U28.11@12576.38,2807.09 12852.02,2807.09 12891.33,2767.78 13022.22,2767.78 13065,2725 13065,2390.25 13046,2371.25 13046,1842 13011.8,1807.8 U20.12@12952.76,1807.8
WPC: U20.10 U29.9 | length 443.4
  Bottom Layer w8: U20.10@12952.76,1707.8 13038.2,1707.8 13065,1681 13252,1681 13275.2,1657.8 U29.9@13374.02,1657.8 U29.9@13375,1656.82
XD0: U1.136 U8.13 | length 1250.4
  Top Layer w8: U1.136@10776.77,1069.21 10931.21,1069.21 10978,1116 10978,1532 11078,1632 11078,1732 11119,1773 11119,1856 11185.7,1922.7 11288.6,1922.7 11296.46,1930.55 U8.13@11296.46,1953.62
XD1: U1.135 U8.14 | length 1137.7
  Top Layer w8: U1.135@10776.77,1049.53 10934.16,1049.53 10994,1109.37 10994,1525.37 11094,1625.37 11094,1708 11141,1755 11141,1828.97 11200.65,1888.62 U8.14@11231.46,1888.62
XD2: U1.134 U8.15 | length 1109.1
  Top Layer w8: U1.134@10776.77,1029.84 10937.1,1029.84 11010,1102.75 11010,1518.75 11110,1618.75 11110,1693 11163,1746 11163,1800.97 11200.65,1838.62 U8.15@11231.46,1838.62
XD3: U1.133 U8.17 | length 1030.5
  Top Layer w8: U1.133@10776.77,1010.16 10940.04,1010.16 11026,1096.12 11026,1512.12 11126,1612.12 11126,1663.97 11200.65,1738.62 U8.17@11231.46,1738.62
XD4: U1.131 U8.18 | length 1010.1
  Top Layer w8: U1.131@10776.77,970.79 10923.3,970.79 11042,1089.49 11042,1505.49 11142,1605.49 11142,1629.97 11200.65,1688.62 U8.18@11231.46,1688.62
XD5: U1.130 U8.19 | length 983.2
  Top Layer w8: U1.130@10776.77,951.1 10926.24,951.1 11058,1082.86 11058,1498.86 11197.76,1638.62 U8.19@11231.46,1638.62
XD6: U1.129 U8.20 | length 970.6
  Top Layer w8: U1.129@10776.77,931.42 10929.18,931.42 11074,1076.24 11074,1492.24 11170.39,1588.62 U8.20@11231.46,1588.62
XD7: U1.128 U8.21 | length 1049.5
  Top Layer w8: U1.128@10776.77,911.73 10932.12,911.73 11090,1069.61 11090,1485.61 11154.39,1550 11288.6,1550 11296.46,1542.15 U8.21@11296.46,1523.62
XTAL1: C3.1 R38.2 U1.111 X3.1 | length 239.2
  Top Layer w10: U1.111@10776.77,577.09 10846.41,577.09 10870,553.5 R38.2@10870,552 10935,552 C3.1@10939,548 X3.1@11003,548
XTAL2: C4.2 R38.1 U1.112 X3.2 | length 243
  Top Layer w10: U1.112@10776.77,596.77 10851.27,596.77 10870,615.5 R38.1@10870,617 10933,617 C4.2@10939,623 X3.2@11008,623
YELLOW50: LED3.2 U40.12 | length 1796
  Top Layer w8: v1(8011,2645) 8012.93,2646.93 8036.97,2646.93 8038.73,2648.69 U40.12@8038.73,2671.43
  Bottom Layer w8: LED3.2@7318.9,3976.38 7318.9,3974.41 7330.65,3962.66 7332.61,3962.66 7391.28,3904 7515.87,3904 7668,3751.87 7668,3336 7788,3216 7788,2781 7925,2644 8010,2644 v1(8011,2645)
pads on no net: CF1.33 CF1.40 CF1.42 CF1.43 CF1.44 CF1.46 J1.48 J1.50 J1.54 J7.61 J7.63 J7.75 J9.16 J9.27 J9.28 SW1.1 U1.2 U1.30 U1.33 U1.35 U1.36 U1.37 U1.41 U1.42 U1.43 U1.44 U1.45 U1.47 U1.48 U1.49 U1.51 U1.55 U1.56 U1.57 U1.77 U1.78 U1.109 U1.114 U1.115 U1.116 U1.124 U1.126 U1.127 U3.11 U3.12 U3.32 U4.11 U4.12 U4.32 U5.11 U5.12 U5.32 U6.11 U6.12 U6.32 U8.1 U8.2 U8.30 U10.2 U10.9 U10.22 U12.1 U12.6 U12.7 U12.24 U12.25 U12.26 U14.15 U17.5 U17.6 U17.9 U17.10 U17.11 U18.5 U18.6 U18.7 U18.9 U18.10 U18.11 U19.4 U19.5 U19.6 U19.11 U19.12 U20.7 U20.9 U20.11 U25.9 U25.10 U25.13 U33.1 U33.2 U33.3 U40.4 U40.6 U40.8 U40.9 U40.10 U40.11 U40.25 VR1.1 VR2.1 X1.1 X2.1
copper on no net:
  other v3: 8809.06,2387.8 9655.51,2387.8 8809.06,3230.31 9655.51,3230.31
  other v4: 5846.46,3153.54 6082.68,3153.54

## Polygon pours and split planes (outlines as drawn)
VCC on Layer 2 "NONET_L-01_P-001" (solid, remove dead copper, pour order 5): 5929,4490 5931,4492 13727,4492 13792,4427 13792,130 13727,65 9471,65 9402,134 9402,1806 9382,1826 6445,1826 6250,2021 6250,3134 6362,3246 6685,3246 6724,3285 7256,3285 7438,3467 7843,3467 7950,3574 8522,3574 8570,3622 8570,3906 8520,3956 7283,3956 7167,3840 7167,3626 7142,3601 6070,3601 5898,3429 5783,3429 5749,3463 5749,4431 5810,4492
NetC26_1 on Layer 2 "NONET_L-01_P-001" (solid, remove dead copper, pour order 0): 5763,2892 5752,2881 5752,956.66 5767.72,940.94 5854.33,940.94 5879,965.61 5879,2878 5865,2892
MCU_ADC1 on Layer 2 "NONET_L-01_P-001" (solid, remove dead copper, pour order 4): 8513,3933 7299,3933 7184,3818 7184,3608 7155,3579 6078,3579 5910,3411 5910,2475 5938,2447 6161,2447 6216,2502 6216,3133 6363,3280 6676,3280 6718,3322 7131,3322 7250,3322 7428,3500 7832,3500 7936,3604 8515,3604 8539,3628 8539,3907
GND on Top Layer "NONET_L-01_P-001" (solid, remove dead copper, pour order 7): 5732.88,161.43 ccw(c5839.18,161.43) 5839.18,55.13 5949.42,55.13 ccw(c5949.42,161.43) 6055.72,161.43 6055.72,1771.67 cw(c6095.09,1771.67) 6095.09,1811.04 9362.8,1811.04 cw(c9362.8,1771.67) 9402.17,1771.67 9402.17,1771.79 9402.17,161.56 ccw(c9508.47,161.56) 9508.47,55.26 13697.45,55.26 ccw(c13697.45,161.56) 13803.75,161.56 13803.75,4397.78 ccw(c13697.45,4397.78) 13697.45,4504.08 5839.18,4504.08 ccw(c5839.18,4397.78) 5732.88,4397.78
VIN on Top Layer "NONET_L-01_P-001" (solid, remove dead copper, pour order 1): 6581,4460 6579,4462 6512,4462 6492,4442 6492,4378 6472,4358 6038,4358 5990,4310 5990,4016 6100,3906 6100,3673 6118,3655 6302,3655 6316,3669 6316,3880 6351,3915 6351,3994 6434,4077 6583,4226 6583,4436
GND on Bottom Layer "NONET_L-01_P-001" (solid, remove dead copper, pour order 8): 5728.31,166 ccw(c5834.61,166) 5834.61,59.7 5944.85,59.7 ccw(c5944.85,166) 6051.15,166 6051.15,1776.24 cw(c6090.52,1776.24) 6090.52,1815.61 9358.24,1815.61 cw(c9358.24,1776.24) 9397.61,1776.24 9397.61,1776.36 9397.61,166.13 ccw(c9503.9,166.13) 9503.91,59.83 13692.88,59.83 ccw(c13692.88,166.13) 13799.18,166.13 13799.18,4402.35 ccw(c13692.88,4402.35) 13692.88,4508.65 5834.61,4508.65 ccw(c5834.61,4402.35) 5728.31,4402.35
VIN5V on Bottom Layer "NONET_L-01_P-001" (solid, remove dead copper, pour order 3): 7489.6,3818 6479,3818 6183,3522 5950,3289 5950,2815 5963,2802 6069,2802 6070,2803 6070,3006 6160,3096 6706,3642 7497,3642 7511,3656 7511,3808.27
GND on Layer 1 "NONET_L-01_P-001" (solid, remove dead copper, pour order 6): 5728.35,161.29 ccw(c5834.65,161.29) 5834.65,54.99 5944.88,54.99 ccw(c5944.88,161.29) 6051.18,161.29 6051.18,1771.53 cw(c6090.55,1771.53) 6090.55,1810.9 9358.27,1810.9 cw(c9358.27,1771.53) 9397.64,1771.53 9397.64,1771.65 9397.64,161.42 ccw(c9503.94,161.42) 9503.94,55.12 13692.91,55.12 ccw(c13692.91,161.42) 13799.21,161.42 13799.21,4397.64 ccw(c13692.91,4397.64) 13692.91,4503.94 5834.65,4503.94 ccw(c5834.65,4397.64) 5728.35,4397.64

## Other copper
Top Layer:
  rectangle net GND: 5775.59,744.09 5988.19,854.33
  rectangle net GND: 8805,3659 8911,3770
  rectangle net GND: 8822,3604 8891,3807
  rectangle net GND: 7826,4000 7960.63,4102
  rectangle net VIN5V: 7377,3634 7458,3787
  rectangle net NetC20_2: 6508,3780 6621,3820
  rectangle net VCC: 8475,3980 8611,4083
  rectangle net VIN5V: 5964,2740 6045,2893
  rectangle net NetC26_1: 5775,2738 5856,2891
  rectangle net V3.7V: 5821.68,1259.84 6019.68,1349.84
  rectangle net VCC: 9576.46,3049 9636.46,3100
  rectangle net VCC: 8730,3049 8790,3100
  region net V3.7V: 5775.59,2555.12 5751.97,2531.5 5751.97,2429.13 5759.84,2421.26 5850.39,2421.26 5866.14,2405.51 5866.14,2295.28 5783.46,2212.6 5783.46,1992.13 5822.83,1952.76 5822.83,1263.78 5826.77,1259.84 6019.68,1259.84 6019.68,1519.69 5956.69,1582.68 5956.69,2007.87 5901.57,2062.99 5901.57,2192.91 5960.63,2251.97 5960.63,2535.43 5940.94,2555.12
  region net NetC18_1: 5980,3745 6072,3745 6081,3736 6081,3665 6127,3619 6136,3619 6118,3601 6100,3619 6025,3619 5965,3679
  region net MCU_ADC1: 8784,4041 8640,4041 8633,4034 8633,3980 8617,3964 8462,3964 8450,3952 8450,3807 8462,3795 8526,3795 8549,3772 8549,3644.99 8568.99,3625 8778,3625 8789,3636 8789,3697 8783,3703 8698,3703 8685,3716 8685,3886 8706,3907 8786,3907 8797,3918 8797,4038
  region net NetC18_1: 6728,3754 6724,3750 6348,3750 6340,3742 6340,3652 6321,3633 6094,3633 5982,3745 5893,3745 5881,3733 5881,3668 5895,3654 5944,3654 6063,3535 6443,3535 6473,3565 6473,3642 6489,3658 6726,3658 6737,3669 6737,3750 6733,3754
  region net NetC26_1: 5816.94,999.36 5777.94,999.36 5773.94,995.36 5773.94,868.36 5776.94,865.36 5815.94,865.36 5821.94,871.36 5821.94,994.36 5817.94,998.36
  region net NetL5_2: 5826.77,1067.92 5826.77,1012 5839.6,999.17 5839.6,875.17 5845.95,868.82 5872.95,868.82 5877.95,873.82 5877.95,960.82 5952.76,1035.63 5952.76,1065.48
  region net NetD4_A: 8425,4083 8425,3656 8405,3636 8282,3636 8282,3702 8167,3817 8167,3824 8212,3869 8239,3869 8309,3939 8309,4072 8320,4083
  region net VIN5V: 8098,4083 8027,4083 7990,4046 7990,4012 7943,3965 7823,3965 7704,3846 7337,3846 7306,3815 7306,3650 7325,3631 7654,3631 7781,3758 7846,3758 7938,3850 8017,3929 8092,3929 8110,3947 8110,4074
  region net NetD3_K: 7746,4098 6883,4098 6817,4032 6817,3919 6784,3886 6591,3886 6591,3846 6593,3844 6789,3844 6817,3816 6817,3698 6860,3655 7268,3655 7286,3673 7286,3834 7320,3868 7700,3868 7760,3928 7760,4090
  region net NetD5_A: 9135,4079 8841,4079 8826,4064 8826,3908 8809,3891 8717,3891 8699,3873 8699,3732 8703,3728 8785,3728 8790,3733 8790,3801 8810,3821 8888,3821 8914,3847 9018,3847 9041,3870 9041,3944 9058,3961 9132,3961 9140,3969 9140,4074
  region net MCU_ADC1: 6159,2555 6158,2556 5998,2556 5990,2548 5989,2548 5989,2372 5994,2367 6078,2367 6081,2370 6081,2461 6091,2471 6164,2471 6166,2473 6166,2549 6160,2555
  region net VCC: 9249,4075 9248,4074 9248,3903 9211,3866 9173,3866 9162,3855 9162,3813 9171,3804 9269,3804 9329,3864 9329,4069 9321,4077 9249,4077
Bottom Layer:
  rectangle net V3.7V: 5826.75,1181.1 6015.75,1346.46
  region net NetC26_1: 5822.83,1000 5771.65,1000 5763.78,992.13 5763.78,913.39 5759.84,909.45 5862.2,909.45 5866.14,913.39 5874.02,913.39 5874.02,921.26 5870.08,925.2 5870.08,952.76 5830.71,992.13 5830.71,996.06

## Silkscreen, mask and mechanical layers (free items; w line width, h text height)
Top Overlay:
  circle w8: c6240.16,3421.26 r78.74
  circle w8: c6240.16,1909.45 r78.74
  circle w8: c9606.3,1909.45 r137.8
  lines w6: 5984.25,4122.05 6023.62,4122.05 6023.62,4161.42 ; 6519.68,3826.77 6519.68,3866.14 6559.06,3866.14
  lines w8: 5728.35,299.21 6031.5,299.21 ; 5728.35,645.67 6051.18,645.67 ; 5728.35,685.04 5763.78,685.04 ; 5728.35,4259.84 5834.65,4259.84 ccw(c5834.65,4397.64) 5972.44,4397.64 5972.44,4503.94 ; 5740.16,1370.08 6039.37,1669.29 ; 5740.16,1488.19 6066.93,1814.96 ; 5740.16,1606.3 5948.82,1814.96 ; 5740.16,1724.41 5830.71,1814.96 ; 6240.16,3578.74 6031.5,3578.74 6031.5,3507.87 6110.24,3507.87 ; 6440.94,2299.21 6488.19,2299.21 ; 6440.94,2527.56 6488.19,2527.56 ; 6440.94,2692.91 6488.19,2692.91 ; 6440.94,2925.2 6488.19,2925.2 ; 6456.69,4122.05 12098.43,4122.05 ; 6464.57,2275.59 6464.57,2322.83 ; 6464.57,2669.29 6464.57,2716.54 ; 6637.8,4338.58 6637.8,4370.08 ; 8555.12,4504.01 8555.12,4397.71 ccw(c8692.91,4397.71) 8830.71,4397.71 ; 8580,2425 8630,2425 ; 8580,3193 8630,3193 ; 8692.91,4397.64 10677.17,4397.64 ; 8830.71,4397.64 8830.71,4503.94 ; 8890,2425 8940,2425 ; 8890,3193 8940,3193 ; 9338.58,1822.83 9338.58,3507.87 ; 9397.64,1771.53 ccw(c9358.27,1771.53) 9358.27,1810.9 6090.55,1810.9 ccw(c6090.55,1771.53) 6051.18,1771.53 6051.18,161.42 cw(c5944.88,161.42) 5944.88,55.12 5834.64,55.12 cw(c5834.64,161.42) 5728.35,161.42 5728.35,4397.64 cw(c5834.65,4397.64) 5834.65,4503.94 13692.91,4503.94 cw(c13692.91,4397.64) 13799.21,4397.64 13799.21,161.42 cw(c13692.91,161.42) 13692.91,55.12 9503.94,55.12 cw(c9503.94,161.42) 9397.64,161.42 9397.64,1771.65 ; 9417.32,299.21 9606.3,299.21 cw(c9606.3,161.42) 9744.09,161.42 9744.09,55.12 ; 9448.82,4122.05 9448.82,2271.65 12157.48,2271.65 ; 10500,4346.46 10500,4370.08 10850.39,4370.08 ; 10539.37,4503.94 10539.37,4397.64 ccw(c10677.17,4397.64) 10814.96,4397.64 10814.96,4503.94 ; 11145.67,55.12 11145.67,177.17 ; 13377.95,1685.04 13417.32,1685.04 13417.32,1645.67 ; 13555.12,55.12 13555.12,161.42 cw(c13692.91,161.42) 13692.91,299.21 13799.21,299.21 ; 13555.12,4503.94 13555.12,4397.64 ccw(c13692.91,4397.64) 13692.91,4259.84 13799.21,4259.84 ; 6110.24,3507.87 6110.24,3578.74 9338.58,3578.74 ; 6110.24,3507.87 9338.58,3507.87 ; 6110.24,3507.87 6110.24,1822.83 9417.32,1822.83 9417.32,3578.74 9338.58,3578.74 ; 9338.58,3507.87 9338.58,3578.74
  lines w10: 10811.02,4370.08 10850.39,4370.08 10850.39,4330.71 ; 12110.24,4122.05 12157.48,4122.05
  text "80" at 8513,3173.67 h60
  text "79" at 8952,3172.67 h60
  text "2" at 8538.94,2408 h60
  text "1" at 8969,2408 h60
  text "Volume" at 6153.64,2130.94 h100
  text "Yamaha OPL3" at 6637.89,2131.03 h100
  text "Mini-ISA/GPIO" at 8543.31,2131.03 h100
Bottom Overlay:
  lines w8: 5728.35,4133.86 6870.08,4133.86 ; 6133.86,4133.86 5728.35,3728.35 13799.21,3728.35 ; 6464.57,3728.35 6870.08,4133.86 ; 6870.08,3728.35 6870.08,4133.86 ; 6905.51,4216.54 6905.51,4177.17 7244.09,4177.17 7244.09,4216.54 ; 6905.51,4405.51 6905.51,4444.88 7244.09,4444.88 7244.09,4405.51 ; 12283.46,4216.54 12283.46,4177.17 12622.05,4177.17 12622.05,4216.54 ; 12283.46,4405.51 12283.46,4444.88 12622.05,4444.88 12622.05,4405.51 ; 13062.99,4133.86 12657.48,3728.35 12657.48,4133.86 13799.21,4133.86 13393.7,3728.35
Mechanical 1:
  circle w8: c6240.16,1909.45 r51.18
  circle w8: c6240.16,3421.26 r51.18
  lines w7: 5834.64,55.12 cw(c5834.64,161.42) 5728.35,161.42 5728.35,4397.64 cw(c5834.65,4397.64) 5834.65,4503.94 13692.91,4503.94 cw(c13692.91,4397.64) 13799.21,4397.64 13799.21,161.42 cw(c13692.91,161.42) 13692.91,55.12 9503.94,55.12 cw(c9503.94,161.42) 9397.64,161.42 9397.64,1771.65 9397.64,1771.53 ccw(c9358.27,1771.53) 9358.27,1810.9 6090.55,1810.9 ccw(c6090.55,1771.53) 6051.18,1771.53 6051.18,161.42 cw(c5944.88,161.42) 5944.88,55.12
  lines w8: 5834.64,55.12 5944.88,55.12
